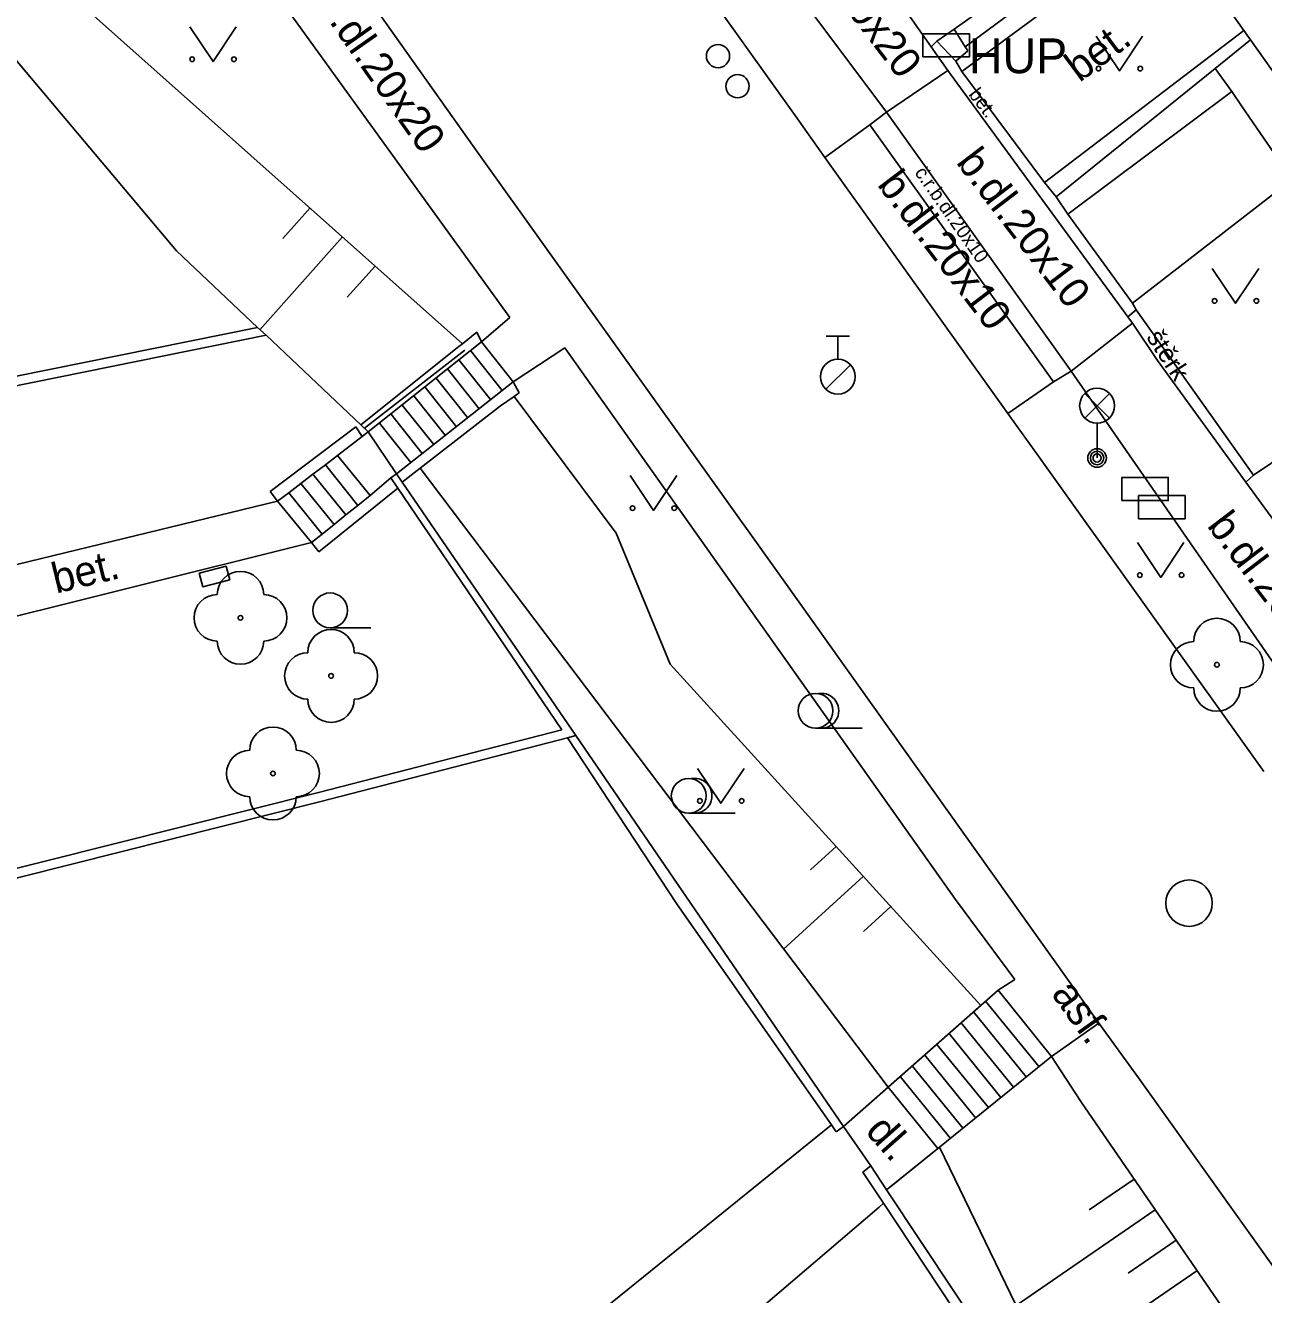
# Model space of a CAD drawing. Extents: x -595546 to -593986, y -1160845 to -1159202.
# Drawn here: x -595331.77 to -595305.12, y -1160447.61 to -1160420.29 of the extents above; entities that cross this region are included whole.
import ezdxf

# ---------------------------------------------------------------- set-up
doc = ezdxf.new("R2010")
doc.units = 0
for name, color, linetype in [('Level 22', 7, 'Continuous'), ('Level 24', 7, 'Continuous'), ('Level 27', 7, 'Continuous'), ('Level 28', 7, 'Continuous'), ('Level 33', 7, 'Continuous'), ('Level 36', 7, 'Continuous'), ('silnoproud - povrch.  znaky a  RIS  skut. velikost', 7, 'Continuous'), ('TM - budovy zdene_ betonove - VP', 7, 'Continuous'), ('TM - chodniky - VP', 7, 'Continuous'), ('TM - dolni hrana svahu', 7, 'Continuous'), ('TM - horni hrana svahu', 7, 'Continuous'), ('TM - komunikace - VP', 7, 'Continuous'), ('TM - plot drateny_ kovovy - VP', 7, 'Continuous'), ('TM - plot dreveny - VP', 7, 'Continuous'), ('TM - podezdivka plotu - VP', 7, 'Continuous'), ('TM - popis objektu', 7, 'Continuous'), ('TM - popis povrchu', 7, 'Continuous'), ('TM - rozhrani mezi zpev. plochami mezi sebou - VP', 7, 'Continuous'), ('TM - rozhrani ploch obecne - VP', 7, 'Continuous'), ('TM - schody - VP', 7, 'Continuous'), ('TM - srafovani', 7, 'Continuous'), ('TM - vjezd na pozemek', 7, 'Continuous'), ('TM - zabradli - VP', 7, 'Continuous'), ('TM - zed operna - VP', 7, 'Continuous')]:
    doc.layers.add(name, color=color, linetype=linetype)

msp = doc.modelspace()

# ---------------------------------------------------------------- linework, layer by layer
at = {"layer": 'Level 22'}
for centre in [(-595327.14, -1160433.04), (-595306.12, -1160434.05), (-595325.19, -1160434.29), (-595326.44, -1160436.39)]:
    msp.add_circle(centre, 0.05, dxfattribs=at)
for centre, start, end in [((-595327.14, -1160432.54), 0, 180), ((-595327.64, -1160433.04), 90, 270), ((-595326.64, -1160433.04), 270, 90), ((-595306.12, -1160433.55), 0, 180), ((-595325.19, -1160433.79), 0, 180), ((-595327.14, -1160433.54), 180, 0), ((-595325.69, -1160434.29), 90, 270), ((-595324.69, -1160434.29), 270, 90), ((-595306.62, -1160434.05), 90, 270), ((-595305.62, -1160434.05), 270, 90), ((-595306.12, -1160434.55), 180, 0), ((-595325.19, -1160434.79), 180, 0), ((-595326.44, -1160435.89), 0, 180), ((-595326.94, -1160436.39), 90, 270), ((-595325.94, -1160436.39), 270, 90), ((-595326.44, -1160436.89), 180, 0)]:
    msp.add_arc(centre, 0.5, start, end, dxfattribs=at)
at = {"layer": 'Level 24'}
for points in [[(-595312.448, -1160420.969), (-595311.448, -1160420.969), (-595311.448, -1160420.469), (-595312.448, -1160420.469)], [(-595308.167, -1160430.518), (-595307.167, -1160430.518), (-595307.167, -1160430.018), (-595308.167, -1160430.018)], [(-595307.807, -1160430.908), (-595306.807, -1160430.908), (-595306.807, -1160430.408), (-595307.807, -1160430.408)]]:
    msp.add_lwpolyline(points, close=True, dxfattribs=at)
at = {"layer": 'Level 27'}
msp.add_circle((-595306.72, -1160439.18), 0.5, dxfattribs=at)
at = {"layer": 'Level 28'}
for p, q in [((-595314.53, -1160426.975), (-595314.03, -1160426.975)), ((-595314.28, -1160427.475), (-595314.28, -1160426.975)), ((-595314.538, -1160428.122), (-595314.008, -1160427.592))]:
    msp.add_line(p, q, dxfattribs=at)
for centre, radius in [((-595316.86, -1160420.95), 0.25), ((-595316.44, -1160421.6), 0.25), ((-595314.28, -1160427.85), 0.375)]:
    msp.add_circle(centre, radius, dxfattribs=at)
at = {"layer": 'Level 33'}
for p, q in [((-595308.965, -1160428.74), (-595308.435, -1160428.21)), ((-595308.965, -1160428.21), (-595308.435, -1160428.74)), ((-595308.7, -1160428.85), (-595308.7, -1160429.6))]:
    msp.add_line(p, q, dxfattribs=at)
for centre, radius in [((-595308.7, -1160428.475), 0.375), ((-595308.7, -1160429.6), 0.2), ((-595308.7, -1160429.6), 0.145), ((-595308.7, -1160429.6), 0.0876)]:
    msp.add_circle(centre, radius, dxfattribs=at)
at = {"layer": 'Level 36'}
for p, q in [((-595325.21, -1160433.255), (-595324.335, -1160433.255)), ((-595314.76, -1160435.415), (-595313.76, -1160435.415)), ((-595317.49, -1160437.245), (-595316.49, -1160437.245))]:
    msp.add_line(p, q, dxfattribs=at)
for points in [[(-595328.23, -1160420.32), (-595327.73, -1160421.07), (-595327.23, -1160420.32)], [(-595308.72, -1160420.52), (-595308.22, -1160421.27), (-595307.72, -1160420.52)], [(-595306.22, -1160425.52), (-595305.72, -1160426.27), (-595305.22, -1160425.52)], [(-595318.75, -1160429.98), (-595318.25, -1160430.73), (-595317.75, -1160429.98)], [(-595307.83, -1160431.42), (-595307.33, -1160432.17), (-595306.83, -1160431.42)], [(-595317.3, -1160436.28), (-595316.8, -1160437.03), (-595316.3, -1160436.28)]]:
    msp.add_lwpolyline(points, dxfattribs=at)
for centre, radius in [((-595328.18, -1160421.02), 0.05), ((-595327.281, -1160421.02), 0.05), ((-595308.67, -1160421.22), 0.05), ((-595307.771, -1160421.22), 0.05), ((-595306.17, -1160426.22), 0.05), ((-595305.271, -1160426.22), 0.05), ((-595318.7, -1160430.68), 0.05), ((-595317.801, -1160430.68), 0.05), ((-595307.78, -1160432.12), 0.05), ((-595306.881, -1160432.12), 0.05), ((-595325.21, -1160432.88), 0.375), ((-595314.76, -1160435.04), 0.375), ((-595317.49, -1160436.87), 0.375), ((-595317.25, -1160436.98), 0.05), ((-595316.351, -1160436.98), 0.05)]:
    msp.add_circle(centre, radius, dxfattribs=at)
for centre in [(-595314.635, -1160435.04), (-595317.365, -1160436.87)]:
    msp.add_arc(centre, 0.375, 260.4059, 99.5941, dxfattribs=at)
at = {"layer": 'silnoproud - povrch.  znaky a  RIS  skut. velikost'}
msp.add_lwpolyline([(-595328.03, -1160432.08), (-595327.45, -1160431.93), (-595327.37, -1160432.22), (-595327.95, -1160432.37), (-595328.03, -1160432.08)], dxfattribs=at)
at = {"layer": 'TM - budovy zdene_ betonove - VP'}
for points in [[(-595305.54, -1160420.4), (-595307.21, -1160418.04)], [(-595305.4, -1160420.6), (-595305.54, -1160420.4)], [(-595300.88, -1160426.97), (-595305.4, -1160420.6)]]:
    msp.add_lwpolyline(points, dxfattribs=at)
at = {"layer": 'TM - chodniky - VP'}
for points in [[(-595316.28, -1160418.08), (-595313.23, -1160422.16)], [(-595327.23, -1160418.42), (-595321.34, -1160426.58)], [(-595311.78, -1160420.37), (-595309.16, -1160418.51)], [(-595311.78, -1160420.37), (-595311.54, -1160420.75)], [(-595311.48, -1160420.84), (-595311.74, -1160421.06)], [(-595311.54, -1160420.75), (-595311.48, -1160420.84)], [(-595311.61, -1160421.28), (-595311.74, -1160421.06)], [(-595313.23, -1160422.16), (-595313.59, -1160422.43)], [(-595313.59, -1160422.43), (-595314.56, -1160423.13)], [(-595321.34, -1160426.58), (-595321.95, -1160427.1)], [(-595321.27, -1160427.96), (-595320.16, -1160427.23)], [(-595320.16, -1160427.23), (-595311.75, -1160439.1)], [(-595309.64, -1160427.96), (-595309.26, -1160427.73)], [(-595309.26, -1160427.73), (-595303.89, -1160435.47)], [(-595310.62, -1160428.64), (-595309.64, -1160427.96)], [(-595324.52, -1160429.14), (-595324.39, -1160429.04)], [(-595305.5, -1160430.12), (-595305.33, -1160429.97)], [(-595302.99, -1160433.56), (-595305.5, -1160430.12)], [(-595311.75, -1160439.1), (-595310.47, -1160440.82)], [(-595310.47, -1160440.82), (-595310.83, -1160441.05)], [(-595311.2, -1160441.38), (-595310.83, -1160441.05)], [(-595313.2, -1160443.14), (-595311.2, -1160441.38)], [(-595309.68, -1160442.48), (-595308.66, -1160441.76)], [(-595309.68, -1160442.48), (-595312.09, -1160444.43)], [(-595314.16, -1160443.99), (-595313.2, -1160443.14)], [(-595327.3, -1160455.08), (-595322.51, -1160450.49), (-595314.42, -1160443.95)], [(-595312.09, -1160444.43), (-595312.13, -1160444.46)], [(-595312.13, -1160444.46), (-595313.23, -1160445.35)], [(-595313.39, -1160445.72), (-595320.68, -1160451.94)], [(-595313.3, -1160445.64), (-595313.39, -1160445.72)]]:
    msp.add_lwpolyline(points, dxfattribs=at)
at = {"layer": 'TM - dolni hrana svahu'}
for points in [[(-595323.27, -1160429.82), (-595313.2, -1160443.14)], [(-595312.09, -1160444.43), (-595307.39, -1160454.14)]]:
    msp.add_lwpolyline(points, dxfattribs=at)
at = {"layer": 'TM - horni hrana svahu'}
for points in [[(-595330.56, -1160419.85), (-595322.36, -1160427.14)], [(-595321.25, -1160428.28), (-595319.05, -1160431.22)], [(-595321.25, -1160428.28), (-595319.05, -1160431.22)], [(-595319.05, -1160431.22), (-595317.89, -1160434.04)], [(-595317.89, -1160434.04), (-595311.2, -1160441.38)], [(-595309.68, -1160442.48), (-595309.05, -1160443.45)], [(-595299.73, -1160457.01), (-595309.05, -1160443.45)]]:
    msp.add_lwpolyline(points, dxfattribs=at)
at = {"layer": 'TM - komunikace - VP'}
for points in [[(-595326.05, -1160417.36), (-595322.11, -1160422.92)], [(-595315.2, -1160422.23), (-595316.88, -1160419.88)], [(-595314.56, -1160423.13), (-595315.2, -1160422.23)], [(-595322.11, -1160422.92), (-595315.46, -1160432.22)], [(-595310.62, -1160428.64), (-595314.56, -1160423.13)], [(-595309.96, -1160429.56), (-595310.62, -1160428.64)], [(-595305.11, -1160436.35), (-595309.96, -1160429.56)], [(-595315.46, -1160432.22), (-595308.66, -1160441.76)], [(-595308.66, -1160441.76), (-595307.81, -1160442.94)], [(-595307.81, -1160442.94), (-595302.1, -1160450.94)]]:
    msp.add_lwpolyline(points, dxfattribs=at)
at = {"layer": 'TM - plot drateny_ kovovy - VP'}
for points in [[(-595328.52, -1160425.14), (-595332.25, -1160420.71)], [(-595326.77, -1160426.79), (-595328.52, -1160425.14)], [(-595334.95, -1160428.65), (-595326.59, -1160426.96)], [(-595326.59, -1160426.96), (-595326.77, -1160426.79)], [(-595324.55, -1160428.89), (-595326.59, -1160426.96)], [(-595324.39, -1160429.04), (-595324.55, -1160428.89)], [(-595323.75, -1160430.25), (-595320.22, -1160435.45)], [(-595320.22, -1160435.45), (-595325.46, -1160436.8)], [(-595320.1, -1160435.62), (-595317.74, -1160439.21)], [(-595325.46, -1160436.8), (-595335.78, -1160439.39)], [(-595317.74, -1160439.21), (-595314.42, -1160443.95)], [(-595314.42, -1160443.95), (-595314.32, -1160444.1)], [(-595313.74, -1160444.97), (-595313.3, -1160445.64)], [(-595313.3, -1160445.64), (-595311.49, -1160448.37)]]:
    msp.add_lwpolyline(points, dxfattribs=at)
at = {"layer": 'TM - plot dreveny - VP'}
for points in [[(-595311.54, -1160420.75), (-595307.44, -1160417.72)], [(-595306.16, -1160421.22), (-595305.4, -1160420.6)], [(-595309.58, -1160423.98), (-595306.16, -1160421.22)], [(-595309.58, -1160423.98), (-595309.83, -1160423.67)], [(-595309.33, -1160424.35), (-595309.58, -1160423.98)], [(-595307.86, -1160426.41), (-595307.94, -1160426.27)], [(-595305.33, -1160429.97), (-595307.86, -1160426.41)], [(-595301.93, -1160427.68), (-595305.33, -1160429.97)]]:
    msp.add_lwpolyline(points, dxfattribs=at)
at = {"layer": 'TM - podezdivka plotu - VP'}
for points in [[(-595311.61, -1160421.28), (-595307.21, -1160418.04)], [(-595309.83, -1160423.67), (-595305.54, -1160420.4)], [(-595334.99, -1160428.45), (-595326.77, -1160426.79)], [(-595322.05, -1160426.89), (-595321.95, -1160427.1)], [(-595324.39, -1160429.04), (-595321.95, -1160427.1)], [(-595323.78, -1160429.94), (-595321.27, -1160427.96)], [(-595321.27, -1160427.96), (-595321.14, -1160428.2)], [(-595324.52, -1160429.14), (-595325.05, -1160429.55)], [(-595324.66, -1160428.93), (-595324.52, -1160429.14)], [(-595325.05, -1160429.55), (-595325.31, -1160429.75), (-595325.58, -1160429.95)], [(-595325.84, -1160430.15), (-595325.58, -1160429.95)], [(-595323.9, -1160430.03), (-595323.78, -1160429.94)], [(-595323.66, -1160430.12), (-595323.78, -1160429.94)], [(-595326.34, -1160430.53), (-595326.1, -1160430.35), (-595325.84, -1160430.15)], [(-595323.9, -1160430.03), (-595324.35, -1160430.41)], [(-595323.9, -1160430.03), (-595323.75, -1160430.25)], [(-595319.92, -1160435.57), (-595323.66, -1160430.12)], [(-595326.34, -1160430.53), (-595326.5, -1160430.32)], [(-595324.35, -1160430.41), (-595324.61, -1160430.62), (-595324.87, -1160430.82)], [(-595325.12, -1160431.03), (-595325.38, -1160431.24), (-595325.61, -1160431.42)], [(-595324.87, -1160430.82), (-595325.12, -1160431.03)], [(-595325.45, -1160431.62), (-595325.61, -1160431.42)], [(-595320.1, -1160435.62), (-595325.41, -1160436.99)], [(-595319.92, -1160435.57), (-595320.1, -1160435.62)], [(-595314.16, -1160443.99), (-595319.92, -1160435.57)], [(-595325.41, -1160436.99), (-595340.47, -1160440.78)], [(-595314.16, -1160443.99), (-595314.32, -1160444.1)], [(-595313.57, -1160444.83), (-595313.74, -1160444.97)], [(-595313.23, -1160445.35), (-595313.57, -1160444.83)], [(-595307.39, -1160454.14), (-595313.23, -1160445.35)]]:
    msp.add_lwpolyline(points, dxfattribs=at)
at = {"layer": 'TM - rozhrani mezi zpev. plochami mezi sebou - VP'}
for points in [[(-595312.27, -1160420.75), (-595312.82, -1160419.98)], [(-595312.27, -1160420.75), (-595312.15, -1160420.63)], [(-595311.91, -1160421.26), (-595312.27, -1160420.75)], [(-595313.23, -1160422.16), (-595311.91, -1160421.26)], [(-595308.04, -1160426.56), (-595311.91, -1160421.26)], [(-595313.23, -1160422.16), (-595309.26, -1160427.73)], [(-595313.59, -1160422.43), (-595309.64, -1160427.96)], [(-595308.04, -1160426.56), (-595307.86, -1160426.41)], [(-595307.94, -1160426.7), (-595308.04, -1160426.56)], [(-595307.94, -1160426.7), (-595309.26, -1160427.73)], [(-595307.4, -1160427.5), (-595307.94, -1160426.7)], [(-595305.5, -1160430.12), (-595307.4, -1160427.5)]]:
    msp.add_lwpolyline(points, dxfattribs=at)
at = {"layer": 'TM - rozhrani ploch obecne - VP'}
for points in [[(-595312.15, -1160420.63), (-595311.78, -1160420.37)], [(-595311.74, -1160421.06), (-595312.15, -1160420.63)], [(-595305.8, -1160421.71), (-595306.16, -1160421.22)], [(-595309.33, -1160424.35), (-595305.8, -1160421.71)], [(-595305.8, -1160421.71), (-595305.58, -1160422.04)], [(-595305.58, -1160422.04), (-595304.5, -1160423.61)], [(-595307.94, -1160426.27), (-595304.5, -1160423.61)], [(-595321.95, -1160427.1), (-595321.27, -1160427.96)], [(-595325.05, -1160429.55), (-595324.35, -1160430.41)], [(-595333.73, -1160432.32), (-595326.34, -1160430.53)], [(-595325.61, -1160431.42), (-595326.34, -1160430.53)], [(-595333.47, -1160433.38), (-595325.61, -1160431.42)], [(-595310.83, -1160441.05), (-595309.68, -1160442.48)], [(-595312.13, -1160444.46), (-595313.2, -1160443.14)]]:
    msp.add_lwpolyline(points, dxfattribs=at)
at = {"layer": 'TM - schody - VP'}
for points in [[(-595322.44, -1160427.49), (-595321.76, -1160428.34)], [(-595322.19, -1160427.29), (-595321.51, -1160428.15)], [(-595322.68, -1160427.68), (-595322, -1160428.54)], [(-595322.93, -1160427.88), (-595322.25, -1160428.73)], [(-595323.41, -1160428.26), (-595322.73, -1160429.11)], [(-595323.17, -1160428.07), (-595322.49, -1160428.93)], [(-595323.66, -1160428.46), (-595322.98, -1160429.31)], [(-595323.47, -1160429.7), (-595324.15, -1160428.85)], [(-595323.9, -1160428.65), (-595323.23, -1160429.5)], [(-595325.58, -1160429.95), (-595324.87, -1160430.82)], [(-595325.31, -1160429.75), (-595324.61, -1160430.62)], [(-595325.84, -1160430.15), (-595325.12, -1160431.03)], [(-595326.1, -1160430.35), (-595325.38, -1160431.24)], [(-595309.95, -1160442.7), (-595311.1, -1160441.29)], [(-595310.23, -1160442.92), (-595311.36, -1160441.52)], [(-595310.77, -1160443.36), (-595311.89, -1160441.98)], [(-595310.5, -1160443.14), (-595311.63, -1160441.75)], [(-595311.04, -1160443.58), (-595312.15, -1160442.22)], [(-595311.31, -1160443.81), (-595312.41, -1160442.45)], [(-595311.58, -1160444.03), (-595312.68, -1160442.68)], [(-595311.85, -1160444.25), (-595312.94, -1160442.91)]]:
    msp.add_lwpolyline(points, dxfattribs=at)
at = {"layer": 'TM - srafovani'}
for points in [[(-595325.64, -1160424.22), (-595326.23, -1160424.88)], [(-595324.94, -1160424.84), (-595326.72, -1160426.84)], [(-595324.24, -1160425.47), (-595324.84, -1160426.14)], [(-595314.32, -1160437.96), (-595314.87, -1160438.46)], [(-595313.73, -1160438.6), (-595315.45, -1160440.17)], [(-595313.14, -1160439.25), (-595313.73, -1160439.79)], [(-595307.9, -1160445.12), (-595308.87, -1160445.78)], [(-595307.45, -1160445.78), (-595310.44, -1160447.84)], [(-595307, -1160446.43), (-595308.03, -1160447.14)], [(-595306.55, -1160447.09), (-595309.74, -1160449.28)]]:
    msp.add_lwpolyline(points, dxfattribs=at)
at = {"layer": 'TM - vjezd na pozemek'}
for points in [[(-595311.61, -1160421.28), (-595309.83, -1160423.67)], [(-595309.33, -1160424.35), (-595307.94, -1160426.27)], [(-595323.78, -1160429.94), (-595324.39, -1160429.04)], [(-595313.57, -1160444.83), (-595314.16, -1160443.99)]]:
    msp.add_lwpolyline(points, dxfattribs=at)
at = {"layer": 'TM - zabradli - VP'}
for points in [[(-595322.31, -1160427.28), (-595324.47, -1160428.96)], [(-595314.16, -1160443.99), (-595310.83, -1160441.05)], [(-595309.68, -1160442.48), (-595312.09, -1160444.43), (-595313.14, -1160445.28)]]:
    msp.add_lwpolyline(points, dxfattribs=at)
at = {"layer": 'TM - zed operna - VP'}
for points in [[(-595322.36, -1160427.14), (-595322.05, -1160426.89)], [(-595322.44, -1160427.2), (-595324.55, -1160428.89)], [(-595322.44, -1160427.2), (-595322.36, -1160427.14)], [(-595321.25, -1160428.28), (-595321.54, -1160428.48)], [(-595321.14, -1160428.2), (-595321.25, -1160428.28)], [(-595323.27, -1160429.82), (-595321.54, -1160428.48)], [(-595326.5, -1160430.32), (-595324.66, -1160428.93)], [(-595323.66, -1160430.12), (-595323.27, -1160429.82)], [(-595325.45, -1160431.62), (-595323.75, -1160430.25)]]:
    msp.add_lwpolyline(points, dxfattribs=at)

# ---------------------------------------------------------------- texts
at = {"layer": 'TM - popis objektu'}
msp.add_text('HUP', height=0.75, dxfattribs=at).set_placement((-595311.46, -1160421.32))
at = {"layer": 'TM - popis povrchu'}
for s, height, rotation, p in [('b.dl.20x20', 0.65, 307.3533, (-595315.38, -1160418.29)), ('b.dl.20x20', 0.65, 305, (-595325.52, -1160419.81)), ('bet.', 0.65, 36.5493, (-595309.08, -1160421.53)), ('bet.', 0.3, 307.6396, (-595311.48, -1160421.78)), ('b.dl.20x10', 0.65, 307.3533, (-595311.75, -1160423.24)), ('b.dl.20x10', 0.65, 307.3533, (-595313.45, -1160423.72)), ('č.r.b.dl.20x10', 0.3, 305, (-595312.64, -1160423.46)), ('štěrk', 0.4, 302.8006, (-595307.65, -1160427)), ('b.dl.20x20', 0.65, 307.3533, (-595306.35, -1160431.06)), ('bet.', 0.65, 13.6159, (-595331.11, -1160432.52)), ('asf.', 0.65, 305.4596, (-595309.7, -1160441.13)), ('dl.', 0.65, 311.5318, (-595313.71, -1160444.1))]:
    msp.add_text(s, height=height, rotation=rotation, dxfattribs=at).set_placement(p)

doc.saveas('drawing.dxf')
